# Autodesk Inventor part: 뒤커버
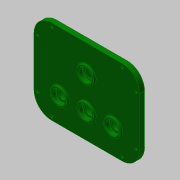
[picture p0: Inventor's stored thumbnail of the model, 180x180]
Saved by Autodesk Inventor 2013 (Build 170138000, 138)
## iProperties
Created: 2016-12
Part Number: 뒤커버
Material: 일반
Document SubType Name: Modeling
Designer: mduedu
Density: 1 g/cm^3
Author: mduedu
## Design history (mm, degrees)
sketch "스케치1"
  geometry: L1 (-90, 42)-(-90, -42); L2 (-60, 72)-(60, 72); L3 (90, 42)-(90, -42); L4 (60, -72)-(-60, -72); A1 r 30 centre (-60, -42) between (-90, -42) and (-60, -72); A2 r 30 centre (60, 42) between (90, 42) and (60, 72); A3 r 30 centre (60, -42) between (60, -72) and (90, -42); A4 r 30 centre (-60, 42) between (-60, 72) and (-90, 42); 1 further point
  constraints: 8 end point, 8 point on circle, 8 tangent, 4 centre point, 3 equal radius, 2 perpendicular, 1 horizontal, 1 vertical
  dimensions: "d80" = 30 radius of A2; "d81" = 144 distance between parallel lines of L4 L2; "d115" = 72 distance from line of L2 point (0, 0); "d116" = 90 distance from line of point (0, 0) L1; "d117" = 180 distance between parallel lines of L3 L1
extrude "돌출1" new body sketch "스케치1" distance "d3" = 10; taper "d4" = 0 deg
sketch "스케치2"
  geometry: C1 r 14 at (0, 26); 1 further point
  constraints: 1 centre point, 1 vertical alignment
  dimensions: "d5" = 28 diameter of C1; "d6" = 26 distance of C1.centre point (0, 0)
extrude "돌출2" join sketch "스케치2" distance "d7" = 3; taper "d8" = 0 deg
sketch "스케치3"
  geometry: C1 r 14 at (0, -28.87); C2 r 14 at (0, 26) reference; C3 r 14 at (-45.552, -28.87); C4 r 14 at (45.552, -28.87); 1 further point
  constraints: 3 centre point, 2 equal radius, 2 horizontal alignment, 1 vertical alignment
  dimensions: "d9" = 28 diameter of C1; "d69" = 54.87 distance of C1.centre C2.centre; "d118" = 45.552 distance of C3.centre C1.centre; "d119" = 45.552 distance of C4.centre C1.centre
extrude "돌출3" join sketch "스케치3" distance "d11" = 3; taper "d12" = 0 deg
hole "구멍1" diameter "d15" = 22; stored, may be unused: countersink angle "d19" = 90 deg, drill point angle "d21" = 0 deg; dims "d13" = 10, "d14" = 10, "d16" = 6, "d17" = 4, "d18" = 2, "d20" = 7
hole "구멍2" diameter "d24" = 18; stored, may be unused: countersink angle "d28" = 90 deg, drill point angle "d30" = 0 deg; dims "d22" = 10, "d23" = 10, "d25" = 6, "d26" = 4, "d27" = 2, "d29" = 1
hole "구멍3" diameter "d33" = 22; stored, may be unused: countersink angle "d37" = 90 deg, drill point angle "d39" = 0 deg; dims "d31" = 10, "d32" = 10, "d34" = 6, "d35" = 4, "d36" = 2, "d38" = 7
hole "구멍7" diameter "d87" = 22; stored, may be unused: countersink angle "d91" = 90 deg, drill point angle "d93" = 0 deg; dims "d88" = 6, "d89" = 4, "d90" = 2, "d92" = 7, "d120" = 10, "d121" = 10
hole "구멍10" diameter "d124" = 22; stored, may be unused: countersink angle "d128" = 90 deg, drill point angle "d130" = 0 deg; dims "d122" = 10, "d123" = 10, "d125" = 6, "d126" = 4, "d127" = 2, "d129" = 7
sketch "스케치4"
  geometry: C1 r 14 at (0, -28.87) reference; C2 r 18 at (0, -28.87); C3 r 14 at (-45.552, -28.87) reference; C4 r 14 at (45.552, -28.87) reference; C5 r 18 at (-45.552, -28.87); C6 r 18 at (45.552, -28.87); 1 further point
  constraints: 3 centre point, 3 coincident
  dimensions: "d40" = 36 diameter of C2; "d131" = 36 diameter of C5; "d132" = 36 diameter of C6
extrude "돌출4" join sketch "스케치4" distance "d41" = 4; taper "d42" = 0 deg
hole "구멍4" diameter "d45" = 22; stored, may be unused: countersink angle "d49" = 90 deg, drill point angle "d51" = 0 deg; dims "d46" = 6, "d47" = 4, "d48" = 2, "d50" = 7.3, "d144" = 10, "d145" = 10
hole "구멍8" diameter "d97" = 22; stored, may be unused: countersink angle "d101" = 90 deg, drill point angle "d103" = 0 deg; dims "d98" = 6, "d99" = 4, "d100" = 2, "d102" = 7.3, "d146" = 10, "d147" = 10
hole "구멍11" diameter "d137" = 22; stored, may be unused: countersink angle "d141" = 90 deg, drill point angle "d143" = 0 deg; dims "d138" = 6, "d139" = 4, "d140" = 2, "d142" = 7.3, "d148" = 10, "d149" = 10
hole "구멍5" diameter "d54" = 15; stored, may be unused: countersink angle "d58" = 90 deg, drill point angle "d60" = 0 deg; dims "d55" = 6, "d56" = 4, "d57" = 2, "d59" = 7, "d150" = 10, "d151" = 10
hole "구멍9" diameter "d106" = 15; stored, may be unused: countersink angle "d110" = 90 deg, drill point angle "d112" = 0 deg; dims "d107" = 6, "d108" = 4, "d109" = 2, "d111" = 7, "d152" = 10, "d153" = 10
hole "구멍12" diameter "d156" = 15; stored, may be unused: countersink angle "d160" = 90 deg, drill point angle "d162" = 0 deg; dims "d154" = 10, "d155" = 10, "d157" = 6, "d158" = 4, "d159" = 2, "d161" = 7
fillet "모깎기1" dims "d61" = 0.3
fillet "모깎기2" dims "d62" = 2
chamfer "모따기1" distance "d63" = 1; stored, may be unused: second distance "d64" = 2, angle "d65" = 45 deg
chamfer "모따기2" distance "d163" = 0.7; stored, may be unused: second distance "d164" = 2, angle "d165" = 30 deg
chamfer "모따기3" distance "d166" = 0.7; stored, may be unused: second distance "d167" = 2, angle "d168" = 30 deg
chamfer "모따기4" distance "d169" = 0.7; stored, may be unused: second distance "d170" = 2, angle "d171" = 30 deg
fillet "모깎기3" dims "d66" = 2
fillet "모깎기4" dims "d67" = 2
fillet "모깎기6" dims "d172" = 2
sketch "스케치5"
  geometry: L1 (-60, 72)-(60, 72) reference; L2 (-90, -42)-(-90, 42) reference; L3 (60, -72)-(-60, -72) reference; L4 (90, 42)-(90, -42) reference; L5 (60, 66)-(-60, 66); L6 (-84, 42)-(-84, -42); L7 (-60, -66)-(60, -66); L8 (84, -42)-(84, 42); A1 r 30 centre (-60, 42) between (-60, 72) and (-90, 42) reference; A2 r 30 centre (-60, -42) between (-90, -42) and (-60, -72) reference; A3 r 30 centre (60, -42) between (60, -72) and (90, -42) reference; A4 r 30 centre (60, 42) between (90, 42) and (60, 72) reference; A5 r 24 centre (-60, 42) between (-60, 66) and (-84, 42); A6 r 24 centre (-60, -42) between (-84, -42) and (-60, -66); A7 r 24 centre (60, -42) between (60, -66) and (84, -42); A8 r 24 centre (60, 42) between (84, 42) and (60, 66)
  constraints: 8 end point, 8 point on circle, 4 centre point, 7 other
  dimensions: "d113" = 6 distance between parallel lines of L6 L2
sketch "스케치6"
  geometry: L1 (60, 66)-(-60, 66) reference; L2 (84, -42)-(84, 42) reference; L3 (-60, -66)-(60, -66) reference; L4 (-84, 42)-(-84, -42) reference; A1 r 24 centre (60, 42) between (84, 42) and (60, 66) reference; A2 r 24 centre (60, -42) between (60, -66) and (84, -42) reference; A3 r 24 centre (-60, -42) between (-84, -42) and (-60, -66) reference; A4 r 24 centre (-60, 42) between (-60, 66) and (-84, 42) reference; 8 further points
  constraints: 8 coincident
hole "구멍6" sketch "스케치6" at (-60, 66), (-84, 42), (-84, -42), (-60, -66), (60, -66), (84, -42), (84, 42), (60, 66) diameter "d71" = 4.5; stored, may be unused: countersink angle "d75" = 90 deg, drill point angle "d77" = 0 deg; dims "d72" = 6, "d73" = 8, "d74" = 4.6, "d76" = 8
node "솔리드1"
